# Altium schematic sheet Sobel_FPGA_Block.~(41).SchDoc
size A1
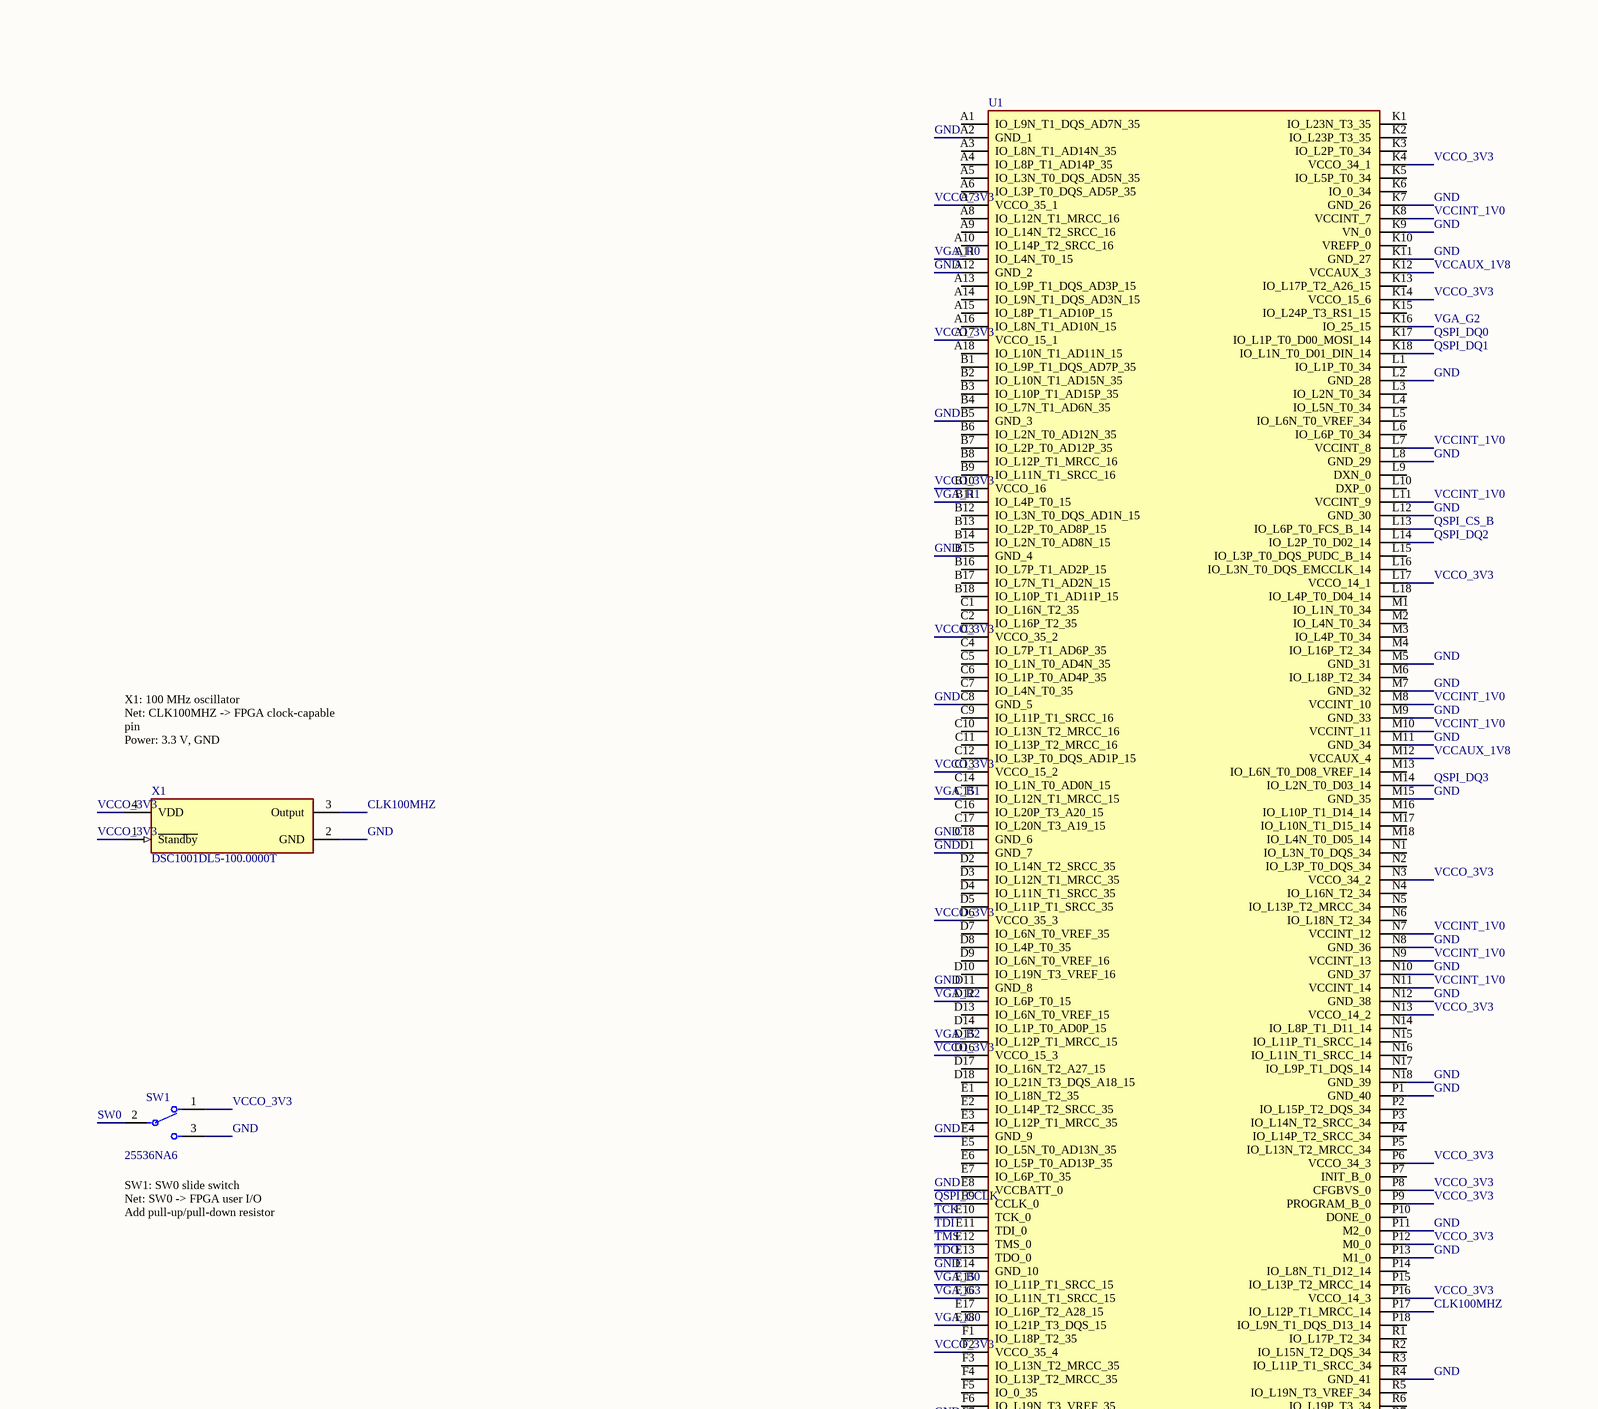
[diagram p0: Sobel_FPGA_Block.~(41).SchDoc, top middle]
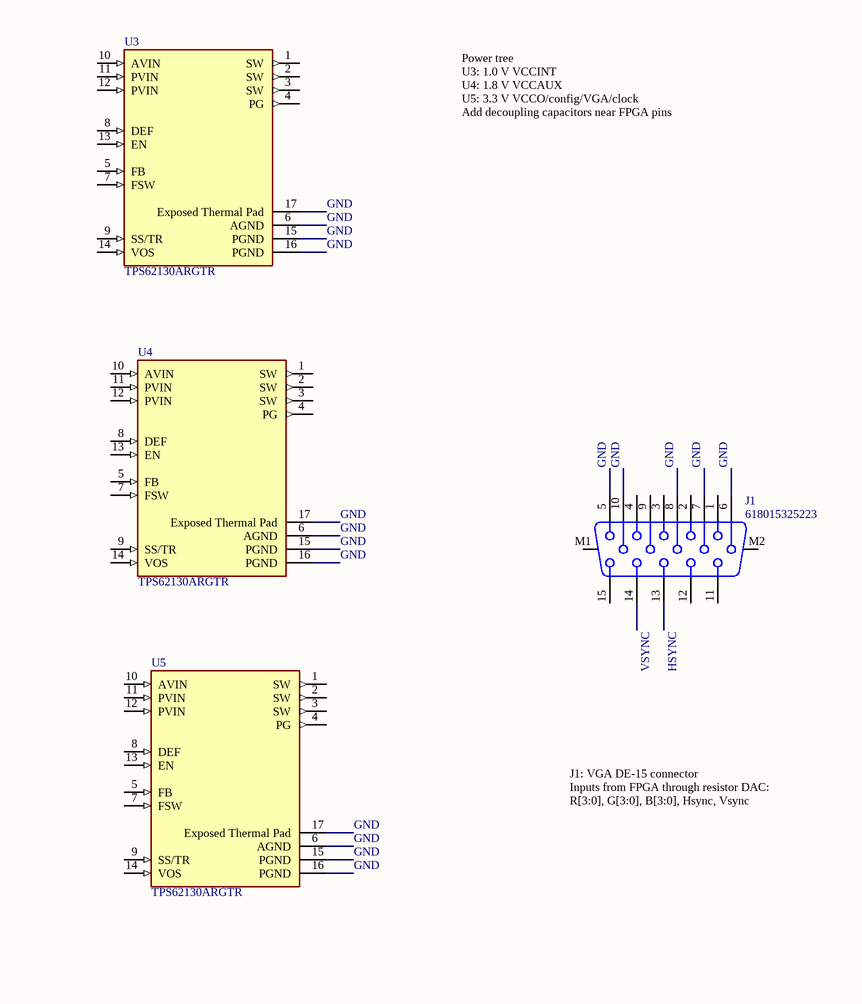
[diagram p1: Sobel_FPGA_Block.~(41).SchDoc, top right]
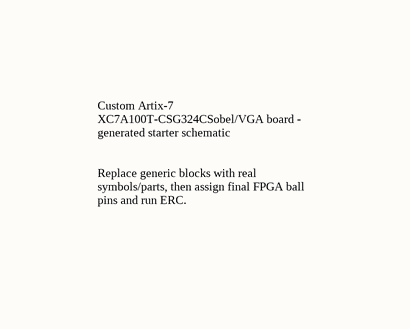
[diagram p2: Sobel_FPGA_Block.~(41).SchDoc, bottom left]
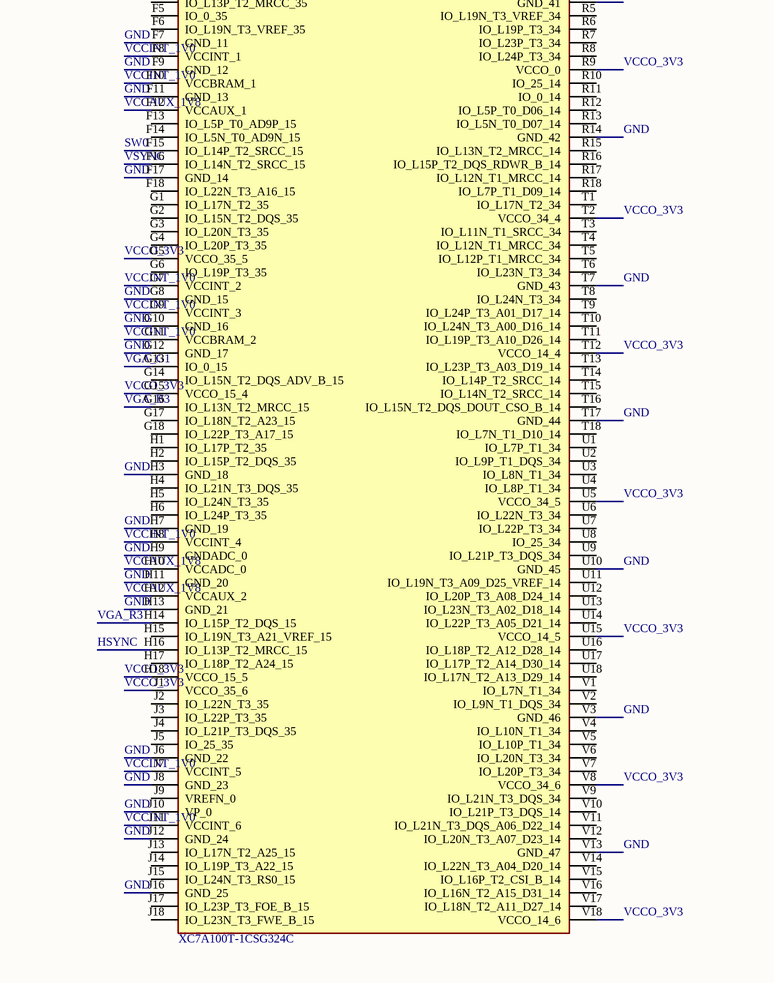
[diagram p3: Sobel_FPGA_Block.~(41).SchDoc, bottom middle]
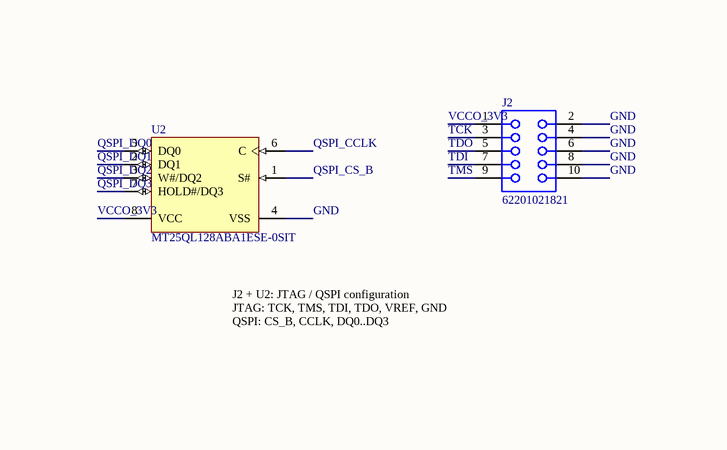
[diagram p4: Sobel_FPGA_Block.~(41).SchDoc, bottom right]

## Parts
J1  618015325223  [618015325223]
J2  62201021821  [62201021821]
SW1  25536NA6  [FP-25536NA6-0]
U1  XC7A100T-1CSG324C  [BGA324C80P18X18_1500X1500X150]
U2  MT25QL128ABA1ESE-0SIT  [MICT-SE-8_M]
U3  TPS62130ARGTR  [FP-RGT0016C-IPC_C]
U4  TPS62130ARGTR  [FP-RGT0016C-IPC_C]
U5  TPS62130ARGTR  [FP-RGT0016C-IPC_C]
X1  DSC1001DL5-100.0000T  [FP-CDFN2520-4LD-PL-1-MFG]

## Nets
CLK100MHZ: U1.P17(IO_L12P_T1_MRCC_14) X1.3(Output)
GND: J1.5 J1.6 J1.7 J1.8 J1.10 J2.2 J2.4 J2.6 J2.8 J2.10 SW1.3 U1.A2(GND_1) U1.A12(GND_2) U1.B5(GND_3) U1.B15(GND_4) U1.C8(GND_5) U1.C18(GND_6) U1.D1(GND_7) U1.D11(GND_8) U1.E4(GND_9) U1.E8(VCCBATT_0) U1.E14(GND_10) U1.F7(GND_11) U1.F9(GND_12) U1.F11(GND_13) U1.F17(GND_14) U1.G8(GND_15) U1.G10(GND_16) U1.G12(GND_17) U1.H3(GND_18) U1.H7(GND_19) U1.H9(GNDADC_0) U1.H11(GND_20) U1.H13(GND_21) U1.J6(GND_22) U1.J8(GND_23) U1.J10(VP_0) U1.J12(GND_24) U1.J16(GND_25) U1.K7(GND_26) U1.K9(VN_0) U1.K11(GND_27) U1.L2(GND_28) U1.L8(GND_29) U1.L12(GND_30) U1.M5(GND_31) U1.M7(GND_32) U1.M9(GND_33) U1.M11(GND_34) U1.M15(GND_35) U1.N8(GND_36) U1.N10(GND_37) U1.N12(GND_38) U1.N18(GND_39) U1.P1(GND_40) U1.P11(M2_0) U1.P13(M1_0) U1.R4(GND_41) U1.R14(GND_42) U1.T7(GND_43) U1.T17(GND_44) U1.U10(GND_45) U1.V3(GND_46) U1.V13(GND_47) U2.4(VSS) U3.6(AGND) U3.15(PGND) U3.16(PGND) U3.17(Exposed_Thermal_Pad) U4.6(AGND) U4.15(PGND) U4.16(PGND) U4.17(Exposed_Thermal_Pad) U5.6(AGND) U5.15(PGND) U5.16(PGND) U5.17(Exposed_Thermal_Pad) X1.2(GND)
HSYNC: J1.13 U1.H16(IO_L13P_T2_MRCC_15)
QSPI_CCLK: U1.E9(CCLK_0) U2.6(C)
QSPI_CS_B: U1.L13(IO_L6P_T0_FCS_B_14) U2.1(S#)
QSPI_DQ0: U1.K17(IO_L1P_T0_D00_MOSI_14) U2.5(DQ0)
QSPI_DQ1: U1.K18(IO_L1N_T0_D01_DIN_14) U2.2(DQ1)
QSPI_DQ2: U1.L14(IO_L2P_T0_D02_14) U2.3(W#/DQ2)
QSPI_DQ3: U1.M14(IO_L2N_T0_D03_14) U2.7(HOLD#/DQ3)
SW0: SW1.2 U1.F15(IO_L14P_T2_SRCC_15)
TCK: J2.3 U1.E10(TCK_0)
TDI: J2.7 U1.E11(TDI_0)
TDO: J2.5 U1.E13(TDO_0)
TMS: J2.9 U1.E12(TMS_0)
VCCAUX_1V8: U1.F12(VCCAUX_1) U1.H10(VCCADC_0) U1.H12(VCCAUX_2) U1.K12(VCCAUX_3) U1.M12(VCCAUX_4)
VCCINT_1V0: U1.F8(VCCINT_1) U1.F10(VCCBRAM_1) U1.G7(VCCINT_2) U1.G9(VCCINT_3) U1.G11(VCCBRAM_2) U1.H8(VCCINT_4) U1.J7(VCCINT_5) U1.J11(VCCINT_6) U1.K8(VCCINT_7) U1.L7(VCCINT_8) U1.L11(VCCINT_9) U1.M8(VCCINT_10) U1.M10(VCCINT_11) U1.N7(VCCINT_12) U1.N9(VCCINT_13) U1.N11(VCCINT_14)
VCCO_3V3: J2.1 SW1.1 U1.A7(VCCO_35_1) U1.A17(VCCO_15_1) U1.B10(VCCO_16) U1.C3(VCCO_35_2) U1.C13(VCCO_15_2) U1.D6(VCCO_35_3) U1.D16(VCCO_15_3) U1.F2(VCCO_35_4) U1.G5(VCCO_35_5) U1.G15(VCCO_15_4) U1.H18(VCCO_15_5) U1.J1(VCCO_35_6) U1.K4(VCCO_34_1) U1.K14(VCCO_15_6) U1.L17(VCCO_14_1) U1.N3(VCCO_34_2) U1.N13(VCCO_14_2) U1.P6(VCCO_34_3) U1.P8(CFGBVS_0) U1.P9(PROGRAM_B_0) U1.P12(M0_0) U1.P16(VCCO_14_3) U1.R9(VCCO_0) U1.T2(VCCO_34_4) U1.T12(VCCO_14_4) U1.U5(VCCO_34_5) U1.U15(VCCO_14_5) U1.V8(VCCO_34_6) U1.V18(VCCO_14_6) U2.8(VCC) X1.1(~{Standby}) X1.4(VDD)
VGA_B0: U1.E15(IO_L11P_T1_SRCC_15)
VGA_B1: U1.C15(IO_L12N_T1_MRCC_15)
VGA_B2: U1.D15(IO_L12P_T1_MRCC_15)
VGA_B3: U1.G16(IO_L13N_T2_MRCC_15)
VGA_G0: U1.E18(IO_L21P_T3_DQS_15)
VGA_G1: U1.G13(IO_0_15)
VGA_G2: U1.K16(IO_25_15)
VGA_G3: U1.E16(IO_L11N_T1_SRCC_15)
VGA_R0: U1.A11(IO_L4N_T0_15)
VGA_R1: U1.B11(IO_L4P_T0_15)
VGA_R2: U1.D12(IO_L6P_T0_15)
VGA_R3: U1.H14(IO_L15P_T2_DQS_15)
VSYNC: J1.14 U1.F16(IO_L14N_T2_SRCC_15)

Not connected (* = marked no-connect by the designer): J1 1 2 3 4 9 11 12 15 M1 M2; U1 A1(IO_L9N_T1_DQS_AD7N_35) A3(IO_L8N_T1_AD14N_35) A4(IO_L8P_T1_AD14P_35) A5(IO_L3N_T0_DQS_AD5N_35) A6(IO_L3P_T0_DQS_AD5P_35) A8(IO_L12N_T1_MRCC_16) A9(IO_L14N_T2_SRCC_16) A10(IO_L14P_T2_SRCC_16) A13(IO_L9P_T1_DQS_AD3P_15) A14(IO_L9N_T1_DQS_AD3N_15) A15(IO_L8P_T1_AD10P_15) A16(IO_L8N_T1_AD10N_15) A18(IO_L10N_T1_AD11N_15) B1(IO_L9P_T1_DQS_AD7P_35) B2(IO_L10N_T1_AD15N_35) B3(IO_L10P_T1_AD15P_35) B4(IO_L7N_T1_AD6N_35) B6(IO_L2N_T0_AD12N_35) B7(IO_L2P_T0_AD12P_35) B8(IO_L12P_T1_MRCC_16) B9(IO_L11N_T1_SRCC_16) B12(IO_L3N_T0_DQS_AD1N_15) B13(IO_L2P_T0_AD8P_15) B14(IO_L2N_T0_AD8N_15) B16(IO_L7P_T1_AD2P_15) B17(IO_L7N_T1_AD2N_15) B18(IO_L10P_T1_AD11P_15) C1(IO_L16N_T2_35) C2(IO_L16P_T2_35) C4(IO_L7P_T1_AD6P_35) C5(IO_L1N_T0_AD4N_35) C6(IO_L1P_T0_AD4P_35) C7(IO_L4N_T0_35) C9(IO_L11P_T1_SRCC_16) C10(IO_L13N_T2_MRCC_16) C11(IO_L13P_T2_MRCC_16) C12(IO_L3P_T0_DQS_AD1P_15) C14(IO_L1N_T0_AD0N_15) C16(IO_L20P_T3_A20_15) C17(IO_L20N_T3_A19_15) D2(IO_L14N_T2_SRCC_35) D3(IO_L12N_T1_MRCC_35) D4(IO_L11N_T1_SRCC_35) D5(IO_L11P_T1_SRCC_35) D7(IO_L6N_T0_VREF_35) D8(IO_L4P_T0_35) D9(IO_L6N_T0_VREF_16) D10(IO_L19N_T3_VREF_16) D13(IO_L6N_T0_VREF_15) D14(IO_L1P_T0_AD0P_15) D17(IO_L16N_T2_A27_15) D18(IO_L21N_T3_DQS_A18_15) E1(IO_L18N_T2_35) E2(IO_L14P_T2_SRCC_35) E3(IO_L12P_T1_MRCC_35) E5(IO_L5N_T0_AD13N_35) E6(IO_L5P_T0_AD13P_35) E7(IO_L6P_T0_35) E17(IO_L16P_T2_A28_15) F1(IO_L18P_T2_35) F3(IO_L13N_T2_MRCC_35) F4(IO_L13P_T2_MRCC_35) F5(IO_0_35) F6(IO_L19N_T3_VREF_35) F13(IO_L5P_T0_AD9P_15) F14(IO_L5N_T0_AD9N_15) F18(IO_L22N_T3_A16_15) G1(IO_L17N_T2_35) G2(IO_L15N_T2_DQS_35) G3(IO_L20N_T3_35) G4(IO_L20P_T3_35) G6(IO_L19P_T3_35) G14(IO_L15N_T2_DQS_ADV_B_15) G17(IO_L18N_T2_A23_15) G18(IO_L22P_T3_A17_15) H1(IO_L17P_T2_35) H2(IO_L15P_T2_DQS_35) H4(IO_L21N_T3_DQS_35) H5(IO_L24N_T3_35) H6(IO_L24P_T3_35) H15(IO_L19N_T3_A21_VREF_15) H17(IO_L18P_T2_A24_15) J2(IO_L22N_T3_35) J3(IO_L22P_T3_35) J4(IO_L21P_T3_DQS_35) J5(IO_25_35) J9(VREFN_0) J13(IO_L17N_T2_A25_15) J14(IO_L19P_T3_A22_15) J15(IO_L24N_T3_RS0_15) J17(IO_L23P_T3_FOE_B_15) J18(IO_L23N_T3_FWE_B_15) K1(IO_L23N_T3_35) K2(IO_L23P_T3_35) K3(IO_L2P_T0_34) K5(IO_L5P_T0_34) K6(IO_0_34) K10(VREFP_0) K13(IO_L17P_T2_A26_15) K15(IO_L24P_T3_RS1_15) L1(IO_L1P_T0_34) L3(IO_L2N_T0_34) L4(IO_L5N_T0_34) L5(IO_L6N_T0_VREF_34) L6(IO_L6P_T0_34) L9(DXN_0) L10(DXP_0) L15(IO_L3P_T0_DQS_PUDC_B_14) L16(IO_L3N_T0_DQS_EMCCLK_14) L18(IO_L4P_T0_D04_14) M1(IO_L1N_T0_34) M2(IO_L4N_T0_34) M3(IO_L4P_T0_34) M4(IO_L16P_T2_34) M6(IO_L18P_T2_34) M13(IO_L6N_T0_D08_VREF_14) M16(IO_L10P_T1_D14_14) M17(IO_L10N_T1_D15_14) M18(IO_L4N_T0_D05_14) N1(IO_L3N_T0_DQS_34) N2(IO_L3P_T0_DQS_34) N4(IO_L16N_T2_34) N5(IO_L13P_T2_MRCC_34) N6(IO_L18N_T2_34) N14(IO_L8P_T1_D11_14) N15(IO_L11P_T1_SRCC_14) N16(IO_L11N_T1_SRCC_14) N17(IO_L9P_T1_DQS_14) P2(IO_L15P_T2_DQS_34) P3(IO_L14N_T2_SRCC_34) P4(IO_L14P_T2_SRCC_34) P5(IO_L13N_T2_MRCC_34) P7(INIT_B_0) P10(DONE_0) P14(IO_L8N_T1_D12_14) P15(IO_L13P_T2_MRCC_14) P18(IO_L9N_T1_DQS_D13_14) R1(IO_L17P_T2_34) R2(IO_L15N_T2_DQS_34) R3(IO_L11P_T1_SRCC_34) R5(IO_L19N_T3_VREF_34) R6(IO_L19P_T3_34) R7(IO_L23P_T3_34) R8(IO_L24P_T3_34) R10(IO_25_14) R11(IO_0_14) R12(IO_L5P_T0_D06_14) R13(IO_L5N_T0_D07_14) R15(IO_L13N_T2_MRCC_14) R16(IO_L15P_T2_DQS_RDWR_B_14) R17(IO_L12N_T1_MRCC_14) R18(IO_L7P_T1_D09_14) T1(IO_L17N_T2_34) T3(IO_L11N_T1_SRCC_34) T4(IO_L12N_T1_MRCC_34) T5(IO_L12P_T1_MRCC_34) T6(IO_L23N_T3_34) T8(IO_L24N_T3_34) T9(IO_L24P_T3_A01_D17_14) T10(IO_L24N_T3_A00_D16_14) T11(IO_L19P_T3_A10_D26_14) T13(IO_L23P_T3_A03_D19_14) T14(IO_L14P_T2_SRCC_14) T15(IO_L14N_T2_SRCC_14) T16(IO_L15N_T2_DQS_DOUT_CSO_B_14) T18(IO_L7N_T1_D10_14) U1(IO_L7P_T1_34) U2(IO_L9P_T1_DQS_34) U3(IO_L8N_T1_34) U4(IO_L8P_T1_34) U6(IO_L22N_T3_34) U7(IO_L22P_T3_34) U8(IO_25_34) U9(IO_L21P_T3_DQS_34) U11(IO_L19N_T3_A09_D25_VREF_14) U12(IO_L20P_T3_A08_D24_14) U13(IO_L23N_T3_A02_D18_14) U14(IO_L22P_T3_A05_D21_14) U16(IO_L18P_T2_A12_D28_14) U17(IO_L17P_T2_A14_D30_14) U18(IO_L17N_T2_A13_D29_14) V1(IO_L7N_T1_34) V2(IO_L9N_T1_DQS_34) V4(IO_L10N_T1_34) V5(IO_L10P_T1_34) V6(IO_L20N_T3_34) V7(IO_L20P_T3_34) V9(IO_L21N_T3_DQS_34) V10(IO_L21P_T3_DQS_14) V11(IO_L21N_T3_DQS_A06_D22_14) V12(IO_L20N_T3_A07_D23_14) V14(IO_L22N_T3_A04_D20_14) V15(IO_L16P_T2_CSI_B_14) V16(IO_L16N_T2_A15_D31_14) V17(IO_L18N_T2_A11_D27_14); U3 1(SW) 2(SW) 3(SW) 4(PG) 5(FB) 7(FSW) 8(DEF) 9(SS/TR) 10(AVIN) 11(PVIN) 12(PVIN) 13(EN) 14(VOS); U4 1(SW) 2(SW) 3(SW) 4(PG) 5(FB) 7(FSW) 8(DEF) 9(SS/TR) 10(AVIN) 11(PVIN) 12(PVIN) 13(EN) 14(VOS); U5 1(SW) 2(SW) 3(SW) 4(PG) 5(FB) 7(FSW) 8(DEF) 9(SS/TR) 10(AVIN) 11(PVIN) 12(PVIN) 13(EN) 14(VOS)

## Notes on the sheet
- Power tree
  U3: 1.0 V VCCINT
  U4: 1.8 V VCCAUX
  U5: 3.3 V VCCO/config/VGA/clock
  Add decoupling capacitors near FPGA pins
- X1: 100 MHz oscillator
  Net: CLK100MHZ -> FPGA clock-capable pin
  Power: 3.3 V, GND
- J1: VGA DE-15 connector
  Inputs from FPGA through resistor DAC:
  R[3:0], G[3:0], B[3:0], Hsync, Vsync
- (near SW1) SW1: SW0 slide switch
  Net: SW0 -> FPGA user I/O
  Add pull-up/pull-down resistor
- Custom Artix-7 XC7A100T-CSG324CSobel/VGA board - generated starter schematic
- Replace generic blocks with real symbols/parts, then assign final FPGA ball pins and run ERC.
- J2 + U2: JTAG / QSPI configuration
  JTAG: TCK, TMS, TDI, TDO, VREF, GND
  QSPI: CS_B, CCLK, DQ0..DQ3

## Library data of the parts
J1 = CMP-002-00072-1: D-sub, Female High Density Angled Pcb Connector Without Hex Screw, 15 Pins
J2 = CMP-002-00073-1: Connector Header Surface Mount 10 position 0.050" (1.27mm)-JTAG Connector; Gender: Female
SW1 = CMP-011-00013-1: Switch Slide ON ON SPDT Side Slide 1A 30VDC 20000Cycles PC Pins Thru-Hole; Max Current Rating: 3A
U1 = XC7A100T-1CSG324C: IC FPGA ARTIX7 210 I/O 324CSBGA; Manufacturer_Name: AMD; Geometry.Height: 1.5mm
U2 = CMP-019-00049-1: 3.6 V 35 mA 128 Mbit 133 MHz Surface Mount FLASH - NOR Memory IC - SOIC-16; Min Supply Voltage: 2.7V; Memory Size: 16MB; Clock Frequency: 133MHz; Max Supply Voltage: 3.6V
U3-U5 = CMP-019-00050-1: 3-V to 17-V, 3-A step-down converter with DCS-control in 3x3 QFN package 16-VQFN -40 to 125; Output Current: 3A; Output Voltage: 6V; Nominal Supply Current: 17µA; Min Supply Voltage: 3V; Max Supply Voltage: 17V
X1 = CMP-00023-00003-1: 3.3 V 100 MHz Surface Mount Low-Power Precision CMOS Oscillator - VDFN-4; Frequency: 100MHz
